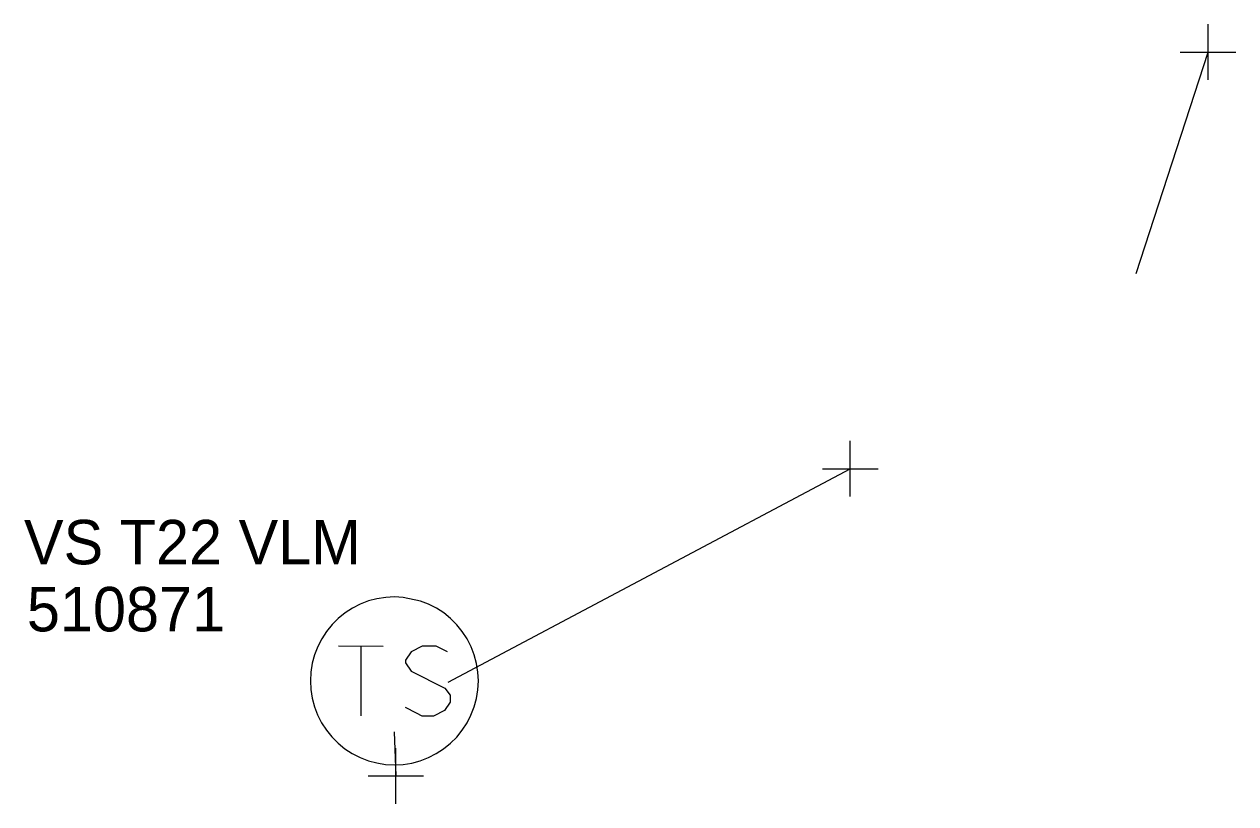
# Model space of a CAD drawing. Extents: x -545577 to -544860, y -1195056 to -1194677.
# Drawn here: x -545334.86 to -545307.59, y -1194862.23 to -1194844.69 of the extents above; entities that cross this region are included whole.
import ezdxf

# ---------------------------------------------------------------- set-up
doc = ezdxf.new("R2010")
doc.units = 0
for name, color, linetype in [('Vrstva 1', 7, 'Continuous'), ('Vrstva 25', 7, 'Continuous'), ('Vrstva 26', 7, 'Continuous'), ('Vrstva 27', 7, 'Continuous'), ('Vrstva 34', 7, 'Continuous'), ('Vrstva 52', 7, 'Continuous'), ('Vrstva 59', 7, 'Continuous'), ('Vrstva 6', 7, 'Continuous')]:
    doc.layers.add(name, color=color, linetype=linetype)

# ---------------------------------------------------------------- blocks, each defined once
blk = doc.blocks.new('NN800')
at = {"layer": 'Vrstva 1'}
for points in [[(-0.442, 0.442), (0.442, -0.442)], [(-0.442, -0.442), (0.442, 0.442)]]:
    blk.add_lwpolyline(points, dxfattribs=at)
blk = doc.blocks.new('NN610')
at = {"layer": 'Vrstva 6'}
for points in [[(1.883, -0.001), (1.872, 0.196), (1.841, 0.392), (1.79, 0.583), (1.718, 0.768), (1.629, 0.943), (1.521, 1.109), (1.397, 1.263), (1.257, 1.403), (1.103, 1.527), (0.937, 1.635), (0.761, 1.725), (0.577, 1.796), (0.19, 1.878), (0.19, 1.878), (-0.007, 1.889), (-0.205, 1.878), (-0.401, 1.847), (-0.591, 1.796), (-0.777, 1.725), (-0.952, 1.635), (-1.118, 1.527), (-1.272, 1.403), (-1.412, 1.263), (-1.536, 1.109), (-1.644, 0.943), (-1.734, 0.768), (-1.805, 0.583), (-1.856, 0.392), (-1.887, 0.196), (-1.898, -0.001), (-1.887, -0.199), (-1.856, -0.395), (-1.805, -0.585), (-1.734, -0.77), (-1.644, -0.946), (-1.536, -1.112), (-1.411, -1.266), (-1.272, -1.405), (-1.118, -1.53), (-0.952, -1.638), (-0.776, -1.728), (-0.591, -1.799), (-0.401, -1.85), (-0.205, -1.881), (-0.007, -1.892), (0.19, -1.881), (0.385, -1.85), (0.577, -1.799), (0.761, -1.728), (0.937, -1.638), (1.103, -1.53), (1.257, -1.405), (1.397, -1.266), (1.521, -1.112), (1.629, -0.946), (1.718, -0.77), (1.79, -0.585), (1.841, -0.395), (1.872, -0.199), (1.883, -0.001)], [(-1.269, 0.782), (-0.261, 0.782)], [(-0.765, 0.782), (-0.765, -0.792)], [(1.188, 0.656), (0.936, 0.782), (0.621, 0.782), (0.369, 0.656), (0.243, 0.468), (0.243, 0.404), (0.369, 0.216), (1.125, -0.162), (1.251, -0.32), (1.251, -0.478), (1.125, -0.666), (0.873, -0.792), (0.621, -0.792), (0.495, -0.73), (0.243, -0.604)]]:
    blk.add_lwpolyline(points, dxfattribs=at)

msp = doc.modelspace()

# ---------------------------------------------------------------- linework, layer by layer
at = {"layer": 'Vrstva 52'}
msp.add_lwpolyline([(-545325.315, -1194859.489), (-545316.265, -1194854.687)], dxfattribs=at)
at = {"layer": 'Vrstva 59'}
for points in [[(-545309.831, -1194850.295), (-545308.214, -1194845.31)], [(-545326.532, -1194860.61), (-545326.494, -1194861.602)]]:
    msp.add_lwpolyline(points, dxfattribs=at)

# ---------------------------------------------------------------- block references
at = {"layer": 'Vrstva 25', "rotation": -0.058288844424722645}
msp.add_blockref('NN610', (-545326.52, -1194859.46), dxfattribs=at)
at = {"layer": 'Vrstva 34'}
for p, rotation in [((-545308.214, -1194845.31), 45), ((-545316.265, -1194854.687), 45), ((-545326.494, -1194861.602), 45.000000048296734)]:
    msp.add_blockref('NN800', p, dxfattribs=dict(at, rotation=rotation))

# ---------------------------------------------------------------- texts
at = {"layer": 'Vrstva 26'}
msp.add_text('510871', height=1, dxfattribs=at).set_placement((-545334.799, -1194858.348))
at = {"layer": 'Vrstva 27'}
msp.add_text('VS T22 VLM', height=1, dxfattribs=at).set_placement((-545334.865, -1194856.839))

doc.saveas('drawing.dxf')
